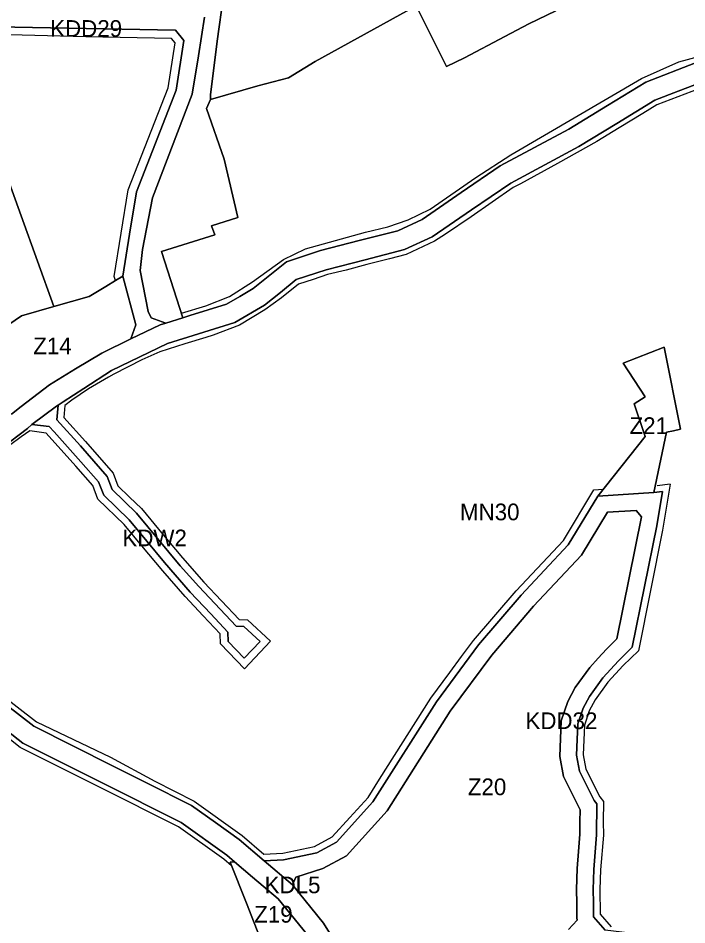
# Model space of a CAD drawing. Extents: x 7428841 to 7433518, y 5545054 to 5546840.
# Drawn here: x 7431082 to 7431482, y 5545462 to 5546005 of the extents above; entities that cross this region are included whole.
import ezdxf

# ---------------------------------------------------------------- set-up
doc = ezdxf.new("R2010")
doc.units = 0
for name, color, linetype in [('linie_rozgraniczajace', 7, 'Continuous'), ('linie_zabudowy_nieprzekraczalne', 7, 'Continuous'), ('oznaczenia_przeznaczen', 7, 'Continuous')]:
    doc.layers.add(name, color=color, linetype=linetype)

msp = doc.modelspace()

# ---------------------------------------------------------------- linework, layer by layer
at = {"layer": 'linie_rozgraniczajace'}
for points in [[(7431205, 5546018.94), (7431201.22, 5545991.64), (7431197.33, 5545959.46), (7431197.19, 5545956.58), (7431194.91, 5545951.21), (7431205.51, 5545920.94), (7431213.71, 5545885.97), (7431197.8, 5545880.89), (7431199.88, 5545875.51), (7431167.99, 5545865.56), (7431180.74, 5545825.82), (7431170.57, 5545822.65), (7431161.64, 5545825.78), (7431159.89, 5545829.63), (7431155.14, 5545854.21), (7431156.45, 5545866.66), (7431162.43, 5545897.75), (7431186.34, 5545959.72), (7431190.03, 5545982.79), (7431193.72, 5546005.85)], [(7431403.99, 5546009.81), (7431387.89, 5546001.96), (7431373.58, 5545994.38), (7431349.31, 5545981.58), (7431338.64, 5545976.38), (7431320.35, 5546012.77), (7431259.87, 5545979.31), (7431244, 5545969.63), (7431225.67, 5545964.88), (7431197.19, 5545956.58), (7431197.33, 5545959.46), (7431201.22, 5545991.64), (7431205, 5546018.94)], [(7431487.65, 5545978.49), (7431457.9, 5545966.94), (7431434.87, 5545952.94), (7431411.84, 5545938.94), (7431391.3, 5545927.87), (7431370.75, 5545916.81), (7431347.38, 5545900.81), (7431324.01, 5545884.82), (7431309.37, 5545878.01), (7431286.21, 5545872.07), (7431263.05, 5545866.14), (7431242.76, 5545859.4), (7431222.76, 5545843.37), (7431214.83, 5545838.68), (7431206.91, 5545833.99), (7431184.88, 5545827.12), (7431180.74, 5545825.82), (7431167.99, 5545865.56), (7431199.88, 5545875.51), (7431197.8, 5545880.89), (7431213.71, 5545885.97), (7431205.51, 5545920.94), (7431194.91, 5545951.21), (7431197.19, 5545956.58), (7431225.67, 5545964.88), (7431244, 5545969.63), (7431259.87, 5545979.31), (7431320.35, 5546012.77), (7431338.64, 5545976.38), (7431349.31, 5545981.58), (7431373.58, 5545994.38), (7431387.89, 5546001.96), (7431403.99, 5546009.81)], [(7431193.72, 5546005.85), (7431190.03, 5545982.79), (7431186.34, 5545959.72), (7431162.43, 5545897.75), (7431156.45, 5545866.66), (7431155.14, 5545854.21), (7431159.89, 5545829.63), (7431161.64, 5545825.78), (7431170.57, 5545822.65), (7431167.15, 5545821.59), (7431149.64, 5545813.17), (7431152.52, 5545821.69), (7431144.77, 5545850.84), (7431148.82, 5545876.03), (7431152.87, 5545901.23), (7431176.62, 5545962.29), (7431181.37, 5545991.93), (7431176.36, 5545998.09), (7431122.76, 5545999.17), (7431069.17, 5546000.25)], [(7431069.17, 5546000.25), (7431122.76, 5545999.17), (7431176.36, 5545998.09), (7431181.37, 5545991.93), (7431176.62, 5545962.29), (7431152.87, 5545901.23), (7431148.82, 5545876.03), (7431144.77, 5545850.84), (7431140.43, 5545848.13), (7431134.63, 5545844.49), (7431124.51, 5545838.5), (7431103.49, 5545832.51), (7431074.14, 5545914.17)], [(7431078.01, 5545768.14), (7431083.98, 5545772.74), (7431100.86, 5545785.75), (7431116.5, 5545795.25), (7431132.13, 5545804.74), (7431149.64, 5545813.17), (7431167.15, 5545821.59), (7431170.57, 5545822.65), (7431180.74, 5545825.82), (7431184.88, 5545827.12), (7431206.91, 5545833.99), (7431214.83, 5545838.68), (7431222.76, 5545843.37), (7431242.76, 5545859.4), (7431263.05, 5545866.14), (7431286.21, 5545872.07), (7431309.37, 5545878.01), (7431324.01, 5545884.82), (7431347.38, 5545900.81), (7431370.75, 5545916.81), (7431391.3, 5545927.87), (7431411.84, 5545938.94), (7431434.87, 5545952.94), (7431457.9, 5545966.94), (7431487.65, 5545978.49)], [(7431072.01, 5545747.44), (7431087.62, 5545759.46), (7431090.23, 5545761.88), (7431100.7, 5545760.73), (7431103.6, 5545757.61), (7431119.63, 5545739.52), (7431130.25, 5545727.55), (7431133.29, 5545719.52), (7431148.53, 5545704.71), (7431169.66, 5545679.21), (7431185.12, 5545661.52), (7431197.47, 5545648.39), (7431207.69, 5545637.5), (7431207.82, 5545631.93), (7431217.38, 5545621.93), (7431226.91, 5545631.97), (7431217.24, 5545640.93), (7431212.57, 5545641.02), (7431190.3, 5545664.83), (7431179.1, 5545677.26), (7431152.91, 5545708.88), (7431138.36, 5545722.95), (7431135.45, 5545730.71), (7431119.49, 5545749.04), (7431105.31, 5545764.72), (7431105.98, 5545773.49), (7431108.95, 5545775.41), (7431121.51, 5545783.56), (7431138.02, 5545794.26), (7431171.56, 5545810.39), (7431211.82, 5545822.95), (7431229.6, 5545833.47), (7431239.09, 5545841.08), (7431248.58, 5545848.69), (7431266.43, 5545854.62), (7431289.93, 5545860.64), (7431313.42, 5545866.66), (7431329.97, 5545874.35), (7431353.49, 5545890.45), (7431377.01, 5545906.55), (7431397.41, 5545917.53), (7431417.81, 5545928.52), (7431440.52, 5545942.33), (7431463.23, 5545956.14), (7431477.3, 5545961.6), (7431491.36, 5545967.06)], [(7431491.36, 5545967.06), (7431477.3, 5545961.6), (7431463.23, 5545956.14), (7431440.52, 5545942.33), (7431417.81, 5545928.52), (7431397.41, 5545917.53), (7431377.01, 5545906.55), (7431353.49, 5545890.45), (7431329.97, 5545874.35), (7431313.42, 5545866.66), (7431289.93, 5545860.64), (7431266.43, 5545854.62), (7431248.58, 5545848.69), (7431239.09, 5545841.08), (7431229.6, 5545833.47), (7431211.82, 5545822.95), (7431171.56, 5545810.39), (7431138.02, 5545794.26), (7431121.51, 5545783.56), (7431108.95, 5545775.41), (7431105.98, 5545773.49), (7431105, 5545772.85), (7431090.23, 5545761.88), (7431087.62, 5545759.46), (7431072.01, 5545747.44)], [(7431420.37, 5545591.94), (7431424.17, 5545599.02), (7431432.12, 5545610.1), (7431441.44, 5545620.34), (7431449.78, 5545628.41), (7431457.1, 5545664.82), (7431464.42, 5545701.24), (7431467.79, 5545721.75), (7431462.75, 5545721.16), (7431470.34, 5545757.31), (7431474.51, 5545758.17), (7431478.62, 5545759.03), (7431468.91, 5545808.18), (7431444.29, 5545798.64), (7431457.56, 5545778.48), (7431451, 5545774.35), (7431457.44, 5545754.74), (7431429.16, 5545718.93), (7431411.45, 5545689.74), (7431397.32, 5545674.7), (7431383.2, 5545659.65), (7431357.77, 5545629.86), (7431332.52, 5545595.8), (7431294.54, 5545535.74), (7431272.72, 5545511.69), (7431261.01, 5545505.29), (7431241.06, 5545501.04), (7431229.38, 5545500.56), (7431214.46, 5545513.28), (7431200.16, 5545523.5), (7431185.87, 5545533.71), (7431158.86, 5545547.28), (7431138.63, 5545557.45), (7431091.4, 5545581.18), (7431059.28, 5545605.97)], [(7431411.64, 5545459.33), (7431416.82, 5545464.92), (7431416.66, 5545466.39), (7431416.51, 5545475.17), (7431416.41, 5545483.38), (7431416.78, 5545495.81), (7431417.62, 5545506.11), (7431418.45, 5545516.41), (7431418.41, 5545523.92), (7431418.5, 5545531.14), (7431408.6, 5545551.04), (7431406.39, 5545563.04), (7431407.3, 5545584.42), (7431411.16, 5545595.93), (7431415.67, 5545604.32), (7431420, 5545610.36), (7431424.34, 5545616.4), (7431429.3, 5545621.85), (7431434.26, 5545627.3), (7431440.62, 5545633.46), (7431455.31, 5545706.57), (7431452.2, 5545710.44), (7431435.01, 5545709.3), (7431419.48, 5545683.7), (7431390.65, 5545652.98), (7431365.6, 5545623.63), (7431340.77, 5545590.14), (7431302.99, 5545530.4), (7431278.67, 5545503.55), (7431264.52, 5545495.82), (7431248.3, 5545490.67), (7431246.37, 5545486.08), (7431229.38, 5545500.56), (7431241.06, 5545501.04), (7431261.01, 5545505.29), (7431272.72, 5545511.69), (7431294.54, 5545535.74), (7431332.52, 5545595.8), (7431357.77, 5545629.86), (7431383.2, 5545659.65), (7431397.32, 5545674.7), (7431411.45, 5545689.74), (7431429.16, 5545718.93), (7431462.75, 5545721.16), (7431467.79, 5545721.75), (7431464.42, 5545701.24), (7431457.1, 5545664.82), (7431449.78, 5545628.41), (7431441.44, 5545620.34), (7431432.12, 5545610.1), (7431424.17, 5545599.02), (7431420.37, 5545591.94), (7431417.23, 5545582.58), (7431416.43, 5545563.75), (7431418.18, 5545554.23), (7431426.88, 5545536.71), (7431428.54, 5545534.6), (7431428.46, 5545516.04), (7431426.77, 5545495.25), (7431426.41, 5545483.29), (7431426.51, 5545475.32), (7431426.65, 5545467.02), (7431433.47, 5545459.03)], [(7431271.51, 5545452.52), (7431264.89, 5545463.23), (7431246.37, 5545486.08), (7431248.3, 5545490.67), (7431264.52, 5545495.82), (7431278.67, 5545503.55), (7431302.99, 5545530.4), (7431340.77, 5545590.14), (7431365.6, 5545623.63), (7431390.65, 5545652.98), (7431419.48, 5545683.7), (7431435.01, 5545709.3), (7431452.2, 5545710.44), (7431455.31, 5545706.57), (7431440.62, 5545633.46), (7431434.26, 5545627.3), (7431429.3, 5545621.85), (7431424.34, 5545616.4), (7431420, 5545610.36), (7431415.67, 5545604.32), (7431411.16, 5545595.93), (7431407.3, 5545584.42), (7431406.39, 5545563.04), (7431408.6, 5545551.04), (7431418.5, 5545531.14), (7431418.41, 5545523.92), (7431418.45, 5545516.41), (7431417.62, 5545506.11), (7431416.78, 5545495.81), (7431416.41, 5545483.38), (7431416.51, 5545475.17), (7431416.66, 5545466.39), (7431416.82, 5545464.92), (7431411.64, 5545459.33)], [(7431059.28, 5545605.97), (7431091.4, 5545581.18), (7431138.63, 5545557.45), (7431158.86, 5545547.28), (7431185.87, 5545533.71), (7431200.16, 5545523.5), (7431214.46, 5545513.28), (7431229.38, 5545500.56), (7431246.37, 5545486.08), (7431264.89, 5545463.23), (7431271.51, 5545452.52)], [(7431050, 5545598.37), (7431084.96, 5545570.99), (7431132.3, 5545547.2), (7431179.65, 5545523.41), (7431207.06, 5545503.82), (7431211.72, 5545499.85), (7431209.11, 5545499.74), (7431218.74, 5545475.08), (7431227.96, 5545451.48)], [(7431255.08, 5545456.28), (7431237.74, 5545477.67), (7431222.4, 5545490.74), (7431211.72, 5545499.85), (7431207.06, 5545503.82), (7431179.65, 5545523.41), (7431132.3, 5545547.2), (7431084.96, 5545570.99), (7431050, 5545598.37)], [(7431485.58, 5545449.26), (7431455.18, 5545456.33), (7431433.47, 5545459.03), (7431426.65, 5545467.02), (7431426.51, 5545475.32), (7431426.41, 5545483.29), (7431426.77, 5545495.25), (7431428.46, 5545516.04), (7431428.54, 5545534.6), (7431426.88, 5545536.71), (7431418.18, 5545554.23), (7431416.43, 5545563.75), (7431417.23, 5545582.58), (7431420.37, 5545591.94)]]:
    msp.add_lwpolyline(points, dxfattribs=at)
for points in [[(7430984.83, 5545877.34), (7430984.91, 5545877.39), (7431070.12, 5545925.35), (7431074.14, 5545914.17), (7431103.49, 5545832.51), (7431084.03, 5545826.97), (7431076.57, 5545821.79), (7431067.88, 5545817.29), (7431045.61, 5545801.14), (7431043.7, 5545803.28), (7431024.84, 5545817.68), (7431005.98, 5545832.07), (7430992.06, 5545855.41), (7430994.9, 5545860.48)], [(7431045.61, 5545801.14), (7431067.88, 5545817.29), (7431076.57, 5545821.79), (7431084.03, 5545826.97), (7431103.49, 5545832.51), (7431124.51, 5545838.5), (7431134.63, 5545844.49), (7431140.43, 5545848.13), (7431144.77, 5545850.84), (7431152.52, 5545821.69), (7431149.64, 5545813.17), (7431132.13, 5545804.74), (7431116.5, 5545795.25), (7431100.86, 5545785.75), (7431083.98, 5545772.74), (7431078.01, 5545768.14), (7431071.09, 5545769), (7431060.22, 5545783.81), (7431049.22, 5545797.1)], [(7431429.16, 5545718.93), (7431457.44, 5545754.74), (7431451, 5545774.35), (7431457.56, 5545778.48), (7431444.29, 5545798.64), (7431468.91, 5545808.18), (7431478.62, 5545759.03), (7431474.51, 5545758.17), (7431470.34, 5545757.31), (7431462.75, 5545721.16)], [(7431090.23, 5545761.88), (7431105, 5545772.85), (7431105.98, 5545773.49), (7431105.31, 5545764.72), (7431119.49, 5545749.04), (7431135.45, 5545730.71), (7431138.36, 5545722.95), (7431152.91, 5545708.88), (7431179.1, 5545677.26), (7431190.3, 5545664.83), (7431212.57, 5545641.02), (7431217.24, 5545640.93), (7431226.91, 5545631.97), (7431217.38, 5545621.93), (7431207.82, 5545631.93), (7431207.69, 5545637.5), (7431197.47, 5545648.39), (7431185.12, 5545661.52), (7431169.66, 5545679.21), (7431148.53, 5545704.71), (7431133.29, 5545719.52), (7431130.25, 5545727.55), (7431119.63, 5545739.52), (7431103.6, 5545757.61), (7431100.7, 5545760.73)], [(7431209.11, 5545499.74), (7431211.72, 5545499.85), (7431222.4, 5545490.74), (7431237.74, 5545477.67), (7431255.08, 5545456.28), (7431256.98, 5545453.19), (7431252.82, 5545446.74), (7431227.96, 5545451.48), (7431218.74, 5545475.08)]]:
    msp.add_lwpolyline(points, close=True, dxfattribs=at)
at = {"layer": 'linie_zabudowy_nieprzekraczalne'}
for points in [[(7431179.86, 5545828.51), (7431194.55, 5545832.95), (7431208.56, 5545838.51), (7431222.38, 5545847.36), (7431241, 5545860.79), (7431254.18, 5545867.16), (7431290.1, 5545877.07), (7431303.51, 5545880.27), (7431315.58, 5545884.55), (7431328.71, 5545890.98), (7431356.1, 5545909.93), (7431377.12, 5545923.45), (7431455.24, 5545969.15), (7431477.61, 5545979.11), (7431507.9, 5545987.31), (7431541.37, 5545997.7), (7431556.39, 5546001.76), (7431567.62, 5546005.71), (7431576.19, 5546009.27), (7431579.49, 5546011.06)], [(7431140.43, 5545848.13), (7431139.67, 5545850.58), (7431148.02, 5545902.54), (7431159.9, 5545933.07), (7431171.84, 5545963.53), (7431176.08, 5545990.51), (7431173.94, 5545993.14), (7431122.65, 5545994.12), (7431061.32, 5545995.73), (7431004.53, 5545996.27), (7430999.01, 5545995.97), (7430951.72, 5545973.41), (7430934.14, 5545965.04)], [(7431489.59, 5545962.96), (7431464.56, 5545953.43), (7431456.2, 5545948.31), (7431441.93, 5545939.68), (7431428.58, 5545931.45), (7431405.03, 5545918.21), (7431382.95, 5545906.08), (7431378.57, 5545903.98), (7431353.35, 5545886.36), (7431338, 5545875.99), (7431331.46, 5545871.74), (7431314.36, 5545863.68), (7431304.37, 5545861.09), (7431290.86, 5545857.78), (7431278.51, 5545854.46), (7431267.28, 5545851.74), (7431258.66, 5545848.87), (7431250.04, 5545846.01), (7431239.8, 5545837.86), (7431229.84, 5545830.67), (7431214.62, 5545821.45), (7431198.88, 5545815.45), (7431194.36, 5545814.08), (7431181.86, 5545810.25), (7431166.92, 5545805.39), (7431156.2, 5545800.7), (7431139.31, 5545792.14), (7431136.1, 5545790.28), (7431124.11, 5545783.34), (7431114.18, 5545776.55)], [(7431114.18, 5545776.55), (7431109.98, 5545773.27), (7431109.43, 5545766.13), (7431122.48, 5545751.69), (7431138.95, 5545732.79), (7431141.79, 5545725.2), (7431148.82, 5545718.4), (7431155.85, 5545711.6), (7431168.99, 5545695.74), (7431180.41, 5545681.95), (7431193.25, 5545667.54), (7431214.34, 5545644.98), (7431219.31, 5545644.8)], [(7431203.23, 5545630.43), (7431203.09, 5545636.56), (7431192.94, 5545647.36), (7431182.16, 5545658.84), (7431168.71, 5545674.24), (7431156.1, 5545689.31), (7431145.59, 5545702), (7431129.87, 5545717.27), (7431126.77, 5545725.44), (7431116.64, 5545736.86), (7431098.81, 5545756.8), (7431089.08, 5545758.16), (7431083.98, 5545754.5)], [(7431083.98, 5545754.5), (7431083.98, 5545754.5), (7431076.84, 5545749.27), (7431067.95, 5545741.69), (7431059.9, 5545734.59), (7431048.2, 5545723.83), (7431039.8, 5545715.27), (7431019.1, 5545693.51), (7431006.28, 5545680.69)], [(7431380.21, 5545662.32), (7431408.53, 5545692.48), (7431426.82, 5545722.78), (7431432.34, 5545723.12)], [(7431464.68, 5545725.39), (7431472.55, 5545726.32)], [(7431472.56, 5545726.24), (7431467.97, 5545698.58)], [(7431467.97, 5545698.58), (7431453.46, 5545626.4), (7431444.32, 5545617.55), (7431435.24, 5545607.58), (7431427.57, 5545596.9), (7431424.05, 5545590.35), (7431421.2, 5545581.85), (7431420.45, 5545564.03), (7431422.01, 5545555.5), (7431430.27, 5545538.86), (7431432.56, 5545535.96), (7431432.41, 5545523.87), (7431432.46, 5545515.89), (7431430.76, 5545495.03), (7431430.41, 5545483.26), (7431430.63, 5545468.52), (7431437.1, 5545460.94)], [(7431291.57, 5545538.43), (7431298.53, 5545549.45), (7431329.14, 5545597.94), (7431340.46, 5545613.37), (7431347.58, 5545622.87), (7431354.73, 5545632.46), (7431380.21, 5545662.32)], [(7431219.31, 5545644.8), (7431233.17, 5545632.16)], [(7431217.57, 5545615.59), (7431203.23, 5545630.43)], [(7431233.17, 5545632.16), (7431217.57, 5545615.59)], [(7431061.75, 5545607.85), (7431093, 5545583.73), (7431137.29, 5545562.66)], [(7431209.77, 5545497.53), (7431205.22, 5545501.45), (7431178.09, 5545520.83), (7431130.72, 5545544.64), (7431083.34, 5545568.44), (7431047.49, 5545596.7)], [(7431137.29, 5545562.66), (7431163.83, 5545548.17)], [(7431163.83, 5545548.17), (7431187.42, 5545536.29), (7431216.31, 5545515.65), (7431229.22, 5545504.56)], [(7431229.22, 5545504.56), (7431240.55, 5545505.02), (7431259.6, 5545509.08), (7431270.1, 5545514.9), (7431280.66, 5545526.4), (7431291.57, 5545538.43)]]:
    msp.add_lwpolyline(points, dxfattribs=at)

# ---------------------------------------------------------------- texts
at = {"layer": 'oznaczenia_przeznaczen'}
for s, p in [('KDD29', (7431101.23, 5545994.17)), ('Z14', (7431091.12, 5545804.01)), ('Z21', (7431448.14, 5545756.22)), ('MN30', (7431346.6, 5545704.52)), ('KDW2', (7431144.49, 5545688.93)), ('KDD32', (7431385.82, 5545579.42)), ('Z20', (7431351.33, 5545539.82)), ('KDL5', (7431229.65, 5545481.08)), ('Z19', (7431223.4, 5545463.46))]:
    msp.add_text(s, height=10, dxfattribs=at).set_placement(p)

doc.saveas('drawing.dxf')
